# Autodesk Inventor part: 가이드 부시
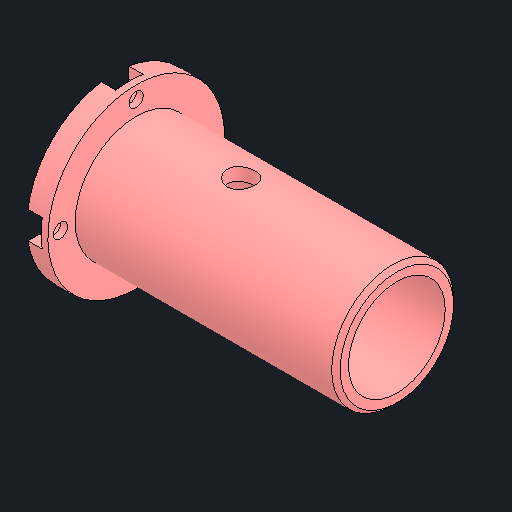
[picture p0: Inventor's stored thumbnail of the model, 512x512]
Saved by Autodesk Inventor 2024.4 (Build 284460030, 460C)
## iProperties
Created: 2026-08
Part Number: 가이드 부시
Material: 강철, 탄소
Document SubType Name: Modeling
Designer: user
Density: 7.85 g/cm^3
Appearance: 기본값
Author: jhkim
Sending System: Autodesk Inventor 2027
Preprocessor: ST-DEVELOPER v20.1
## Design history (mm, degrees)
feature "솔리드1"
node "솔리드2"
